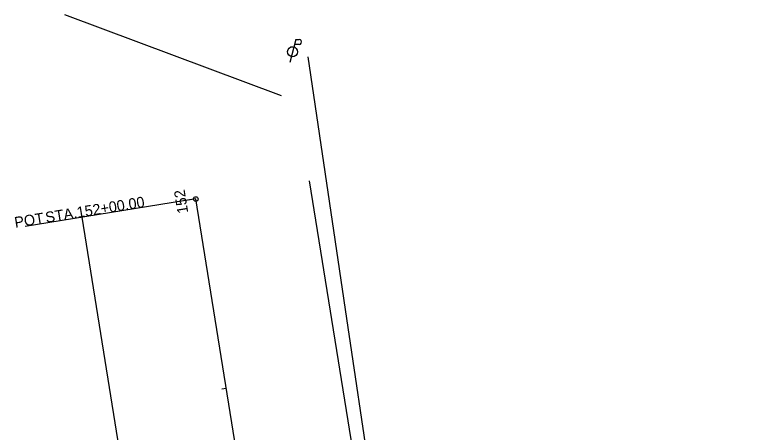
# Model space of a CAD drawing. Extents: x 2030588 to 2035216, y 462285 to 465007.
# Drawn here: x 2031145.6 to 2031337.9, y 464615.7 to 464724.5 of the extents above; entities that cross this region are included whole.
import ezdxf

# ---------------------------------------------------------------- set-up
doc = ezdxf.new("R2010")
doc.units = 0
for name, color, linetype in [('DR_X_Storm_Sewer', 7, 'Continuous'), ('RW_X_CL', 7, 'Continuous'), ('RW_X_CL_100_Cardinal_Points', 7, 'Continuous'), ('RW_X_CL_100_Stations', 7, 'Continuous'), ('RW_X_Esmt_SH', 7, 'Continuous'), ('UT_X_Electric', 7, 'Continuous'), ('UT_X_Electric_Cells', 7, 'Continuous')]:
    doc.layers.add(name, color=color, linetype=linetype)

msp = doc.modelspace()

# ---------------------------------------------------------------- linework, layer by layer
at = {"layer": 'DR_X_Storm_Sewer'}
msp.add_line((2031215, 464703.3), (2031158.63, 464724.46), dxfattribs=at)
at = {"layer": 'RW_X_CL'}
msp.add_line((2031264.45, 464230.53), (2031192.71, 464676.45), dxfattribs=at)
at = {"layer": 'RW_X_CL_100_Cardinal_Points'}
msp.add_line((2031192.71, 464676.45), (2031148.29, 464669.31), dxfattribs=at)
msp.add_ellipse((2031192.71, 464676.45), major_axis=(-0.401, 0.447), ratio=0.999987, dxfattribs=at)
at = {"layer": 'RW_X_CL_100_Stations'}
for p, q in [((2031192.71, 464676.45), (2031190.74, 464676.14)), ((2031200.65, 464627.09), (2031199.47, 464626.9))]:
    msp.add_line(p, q, dxfattribs=at)
at = {"layer": 'RW_X_Esmt_SH'}
for p, q in [((2031294.07, 464235.3), (2031222.33, 464681.22)), ((2031234.84, 464225.77), (2031163.1, 464671.69))]:
    msp.add_line(p, q, dxfattribs=at)
at = {"layer": 'UT_X_Electric'}
msp.add_lwpolyline([(2031221.84, 464713.47), (2031231.94, 464645.28), (2031244.28, 464562.24), (2031252.85, 464504.34), (2031260, 464456.22), (2031264.87, 464423.29), (2031269.31, 464393.31), (2031274.04, 464361.48), (2031280.97, 464314.78), (2031288.22, 464265.92), (2031292.23, 464240.82), (2031300.29, 464190.3), (2031337.85, 463955.94)], dxfattribs=at)
at = {"layer": 'UT_X_Electric_Cells'}
for p, q in [((2031218.77, 464718.03), (2031217.16, 464712.03)), ((2031218.77, 464718.03), (2031219.62, 464718.03)), ((2031218.43, 464716.76), (2031219.62, 464716.76))]:
    msp.add_line(p, q, dxfattribs=at)
msp.add_ellipse((2031219.63, 464717.39), major_axis=(-0.426, 0.474), ratio=0.999987, start_param=2.390496, end_param=5.571299, dxfattribs=at)
msp.add_ellipse((2031217.91, 464714.83), major_axis=(-0.868, 0.967), ratio=0.999987, dxfattribs=at)

# ---------------------------------------------------------------- texts
at = {"layer": 'RW_X_CL_100_Cardinal_Points'}
for s, p in [('152+00.00', (2031161.96, 464671.54)), ('POT', (2031145.72, 464668.93)), (' STA. ', (2031152.75, 464670.06))]:
    msp.add_text(s, height=2.8, rotation=9.1388, dxfattribs=at).set_placement(p)
at = {"layer": 'RW_X_CL_100_Stations'}
msp.add_text('152', height=2.8, rotation=99.1395, dxfattribs=at).set_placement((2031190.76, 464672.89))

doc.saveas('drawing.dxf')
